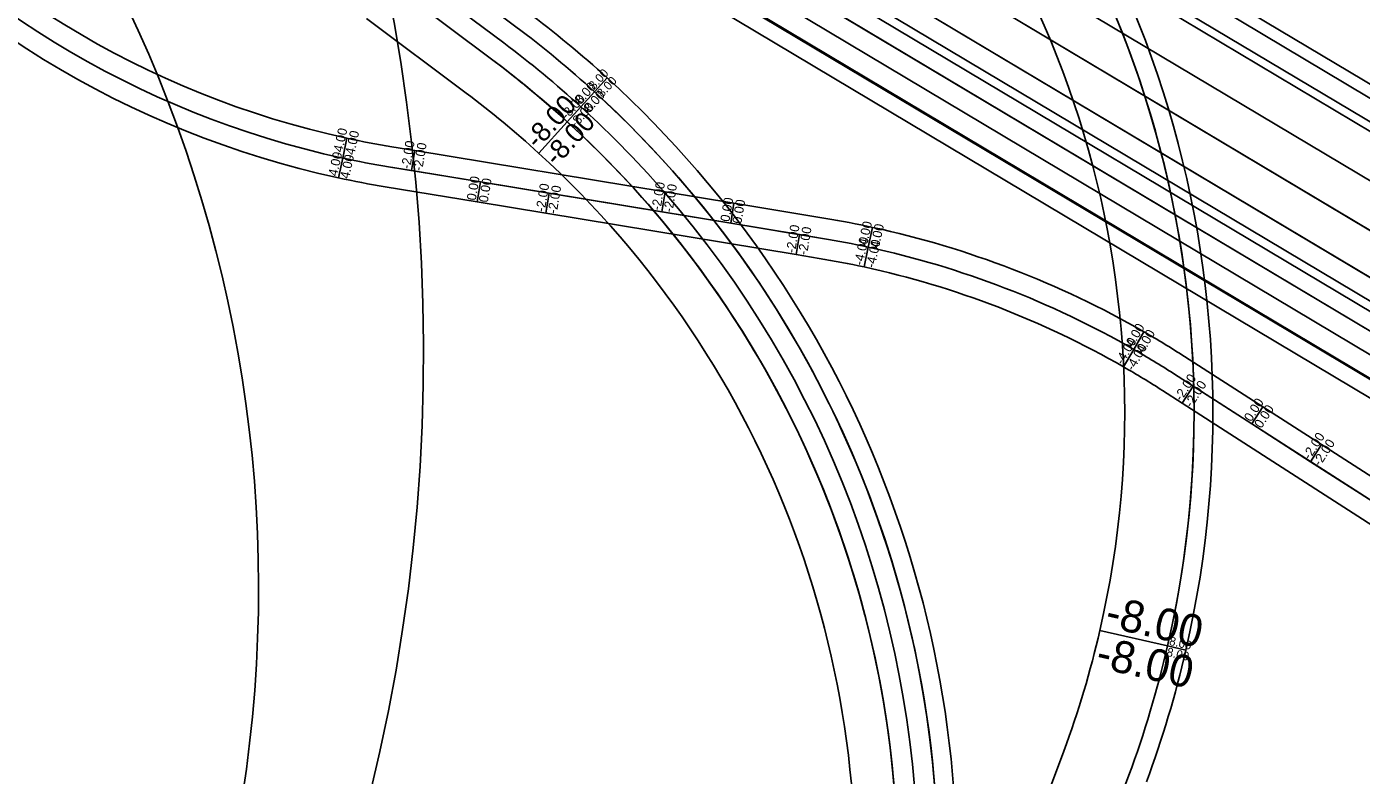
# Model space of a CAD drawing. Extents: x 2342222 to 2351711, y 366548 to 372860.
# Drawn here: x 2346266 to 2347057, y 369068 to 369511 of the extents above; entities that cross this region are included whole.
import ezdxf

# ---------------------------------------------------------------- set-up
doc = ezdxf.new("R2010")
doc.units = 0
for name, color, linetype in [('RD_HC_Cl', 7, 'Continuous'), ('RD_PD_Final_LnLine', 7, 'Continuous'), ('RD_PD_SuperShp_BL_EB_526', 7, 'Continuous'), ('RD_PD_SuperShp_BL_WB_526', 7, 'Continuous'), ('RD_PD_SuperShp_EB_526', 7, 'Continuous'), ('RD_PD_SuperShp_LINE-A', 7, 'Continuous'), ('RD_PD_SuperShp_Line-B', 7, 'Continuous'), ('RD_PD_SuperShp_REL_L-2118', 7, 'Continuous'), ('RD_PD_SuperShp_REL_LINE-3', 7, 'Continuous'), ('RD_PD_SuperShp_WB_526', 7, 'Continuous')]:
    doc.layers.add(name, color=color, linetype=linetype)

msp = doc.modelspace()

# ---------------------------------------------------------------- linework, layer by layer
at = {"layer": 'RD_HC_Cl'}
for centre, radius, start, end in [((2345401.07, 369318.89), 1100, 337.175, 58.13524), ((2345401.07, 369318.89), 1100, 337.175, 58.13524), ((2345603.44, 369178.93), 800, 339.77456, 51.32478), ((2345603.44, 369178.93), 800, 339.77456, 51.32478)]:
    msp.add_arc(centre, radius, start, end, dxfattribs=at)
at = {"layer": 'RD_PD_Final_LnLine'}
msp.add_line((2346236.75, 369794.56), (2347945.19, 368775.26), dxfattribs=at)
msp.add_line((2346236.75, 369794.56), (2347945.19, 368775.26), dxfattribs=at)
msp.add_arc((2346182.01, 369011.56), 600, 321.09378, 53.19179, dxfattribs=at)
at = {"layer": 'RD_PD_SuperShp_BL_EB_526'}
for p, q in [((2348273.55, 368639.71), (2346276.99, 369830.91)), ((2346270.85, 369820.6), (2348267.44, 368629.38)), ((2346351.12, 369814.63), (2348285.99, 368660.23)), ((2348273.55, 368639.71), (2346338.83, 369794.02)), ((2347092.44, 369401.64), (2346692.07, 369640.52)), ((2346679.17, 369618.9), (2347079.55, 369380.03))]:
    msp.add_line(p, q, dxfattribs=at)
at = {"layer": 'RD_PD_SuperShp_BL_WB_526'}
for p, q in [((2348323.93, 368724.15), (2346306.76, 369927.65)), ((2346294.47, 369907.04), (2348311.78, 368703.46)), ((2347105.34, 369423.25), (2346704.96, 369662.13)), ((2346692.07, 369640.52), (2347092.44, 369401.64))]:
    msp.add_line(p, q, dxfattribs=at)
at = {"layer": 'RD_PD_SuperShp_EB_526'}
for p, q in [((2348285.94, 368660.26), (2346335.92, 369823.7)), ((2346323.32, 369803.27), (2348273.49, 368639.75)), ((2346323.62, 369803.09), (2348273.49, 368639.75))]:
    msp.add_line(p, q, dxfattribs=at)
at = {"layer": 'RD_PD_SuperShp_LINE-A'}
for p, q in [((2346901.84, 369153.72), (2346941.92, 369144.5)), ((2346941.92, 369144.5), (2346901.84, 369153.72)), ((2346941.92, 369144.5), (2346952.76, 369142)), ((2346952.76, 369142), (2346941.92, 369144.5)), ((2346880.42, 369082.26), (2346846.34, 368990.65)), ((2346884.88, 368976.31), (2346918.97, 369067.92))]:
    msp.add_line(p, q, dxfattribs=at)
for radius, start, end in [(627.13, 347.0341, 50.18223), (616, 347.0341, 50.18223), (574.88, 347.0341, 50.18223), (616, 347.0341, 25.02373), (574.88, 339.59346, 347.0341), (616, 339.59346, 347.0341), (616, 339.59346, 347.0341), (627.13, 339.59346, 347.0341)]:
    msp.add_arc((2346341.62, 369282.71), radius, start, end, dxfattribs=at)
at = {"layer": 'RD_PD_SuperShp_Line-B'}
for p, q in [((2346496.91, 369555.28), (2346555.87, 369511.16)), ((2346548.69, 369501.55), (2346489.72, 369545.67)), ((2346489.72, 369545.67), (2346548.69, 369501.55)), ((2346541.5, 369491.94), (2346482.53, 369536.06)), ((2346541.5, 369491.94), (2346482.53, 369536.06)), ((2346467.48, 369515.95), (2346526.44, 369471.83)), ((2346602.5, 369472.61), (2346610, 369480.83)), ((2346610, 369480.83), (2346602.5, 369472.61)), ((2346602.5, 369472.61), (2346594.41, 369463.74)), ((2346594.41, 369463.74), (2346602.5, 369472.61)), ((2346594.41, 369463.74), (2346586.33, 369454.87)), ((2346586.33, 369454.87), (2346594.41, 369463.74)), ((2346569.4, 369436.31), (2346586.33, 369454.87)), ((2346586.33, 369454.87), (2346569.4, 369436.31))]:
    msp.add_line(p, q, dxfattribs=at)
for radius, start, end in [(635.13, 47.63463, 53.19179), (624, 47.63463, 53.19179), (624, 47.63463, 53.19179), (612, 47.63463, 53.19179), (612, 47.63463, 53.19179), (600, 47.63463, 53.19179), (600, 47.63463, 53.19179), (635.13, 353.08954, 47.63463), (574.88, 47.63463, 53.19179), (624, 326.65285, 47.63463), (624, 353.08954, 47.63463), (612, 326.65285, 47.63463), (612, 326.65285, 47.63463), (600, 326.65285, 47.63463), (600, 353.08954, 47.63463), (574.88, 353.08954, 47.63463)]:
    msp.add_arc((2346182.01, 369011.56), radius, start, end, dxfattribs=at)
at = {"layer": 'RD_PD_SuperShp_REL_L-2118'}
for p, q in [((2346455.86, 369445.11), (2346453.32, 369433.38)), ((2346455.86, 369445.11), (2346453.32, 369433.38)), ((2346495.98, 369437.81), (2346482.37, 369440.05)), ((2346450.78, 369421.65), (2346453.32, 369433.38)), ((2346450.78, 369421.65), (2346453.32, 369433.38)), ((2346494.02, 369425.97), (2346495.98, 369437.81)), ((2346494.02, 369425.97), (2346495.98, 369437.81)), ((2346495.98, 369437.81), (2346644.26, 369413.35)), ((2346480.41, 369428.21), (2346494.02, 369425.97)), ((2346480.41, 369428.21), (2346534.85, 369419.23)), ((2346642.31, 369401.51), (2346494.02, 369425.97)), ((2346532.9, 369407.39), (2346478.46, 369416.37)), ((2346534.85, 369419.23), (2346532.9, 369407.39)), ((2346532.9, 369407.39), (2346534.85, 369419.23)), ((2346534.85, 369419.23), (2346575.67, 369412.5)), ((2346575.67, 369412.5), (2346573.72, 369400.66)), ((2346573.72, 369400.66), (2346575.67, 369412.5)), ((2346575.67, 369412.5), (2346723.96, 369388.04)), ((2346644.26, 369413.35), (2346642.31, 369401.51)), ((2346642.31, 369401.51), (2346644.26, 369413.35)), ((2346644.26, 369413.35), (2346685.08, 369406.62)), ((2346573.72, 369400.66), (2346532.9, 369407.39)), ((2346722, 369376.2), (2346573.72, 369400.66)), ((2346683.13, 369394.78), (2346642.31, 369401.51)), ((2346685.08, 369406.62), (2346683.13, 369394.78)), ((2346683.13, 369394.78), (2346685.08, 369406.62)), ((2346685.08, 369406.62), (2346739.54, 369397.63)), ((2346737.58, 369385.79), (2346683.13, 369394.78)), ((2346767.21, 369392.36), (2346764.66, 369380.63)), ((2346764.66, 369380.63), (2346767.21, 369392.36)), ((2346723.96, 369388.04), (2346722, 369376.2)), ((2346722, 369376.2), (2346723.96, 369388.04)), ((2346723.96, 369388.04), (2346737.58, 369385.79)), ((2346735.63, 369373.95), (2346722, 369376.2)), ((2346764.66, 369380.63), (2346762.12, 369368.9)), ((2346762.12, 369368.9), (2346764.66, 369380.63)), ((2346927.86, 369330.53), (2346921.89, 369320.13)), ((2346921.89, 369320.13), (2346927.86, 369330.53)), ((2346921.89, 369320.13), (2346915.91, 369309.72)), ((2346921.89, 369320.13), (2346915.91, 369309.72)), ((2346951.94, 369315.89), (2346998.36, 369286.06)), ((2346991.87, 369275.97), (2346945.46, 369305.8)), ((2346957.06, 369298.34), (2346945.46, 369305.8)), ((2346950.57, 369288.24), (2346957.06, 369298.34)), ((2346950.57, 369288.24), (2346957.06, 369298.34)), ((2346957.06, 369298.34), (2347131.86, 369185.99)), ((2346938.97, 369295.7), (2346950.57, 369288.24)), ((2347125.37, 369175.89), (2346950.57, 369288.24)), ((2346998.36, 369286.06), (2346991.87, 369275.97)), ((2346991.87, 369275.97), (2346998.36, 369286.06)), ((2346998.36, 369286.06), (2347033.16, 369263.69)), ((2347026.67, 369253.6), (2346991.87, 369275.97)), ((2347033.16, 369263.69), (2347026.67, 369253.6)), ((2347026.67, 369253.6), (2347033.16, 369263.69)), ((2347033.16, 369263.69), (2347138.35, 369196.08)), ((2347131.86, 369185.99), (2347026.67, 369253.6))]:
    msp.add_line(p, q, dxfattribs=at)
for centre, radius, start, end in [((2346569.92, 369970.88), 538, 219.20131, 257.76033), ((2346569.92, 369970.88), 550, 219.20131, 257.76033), ((2346569.92, 369970.88), 550, 219.20131, 257.76033), ((2346569.92, 369970.88), 562, 219.20131, 257.76033), ((2346569.92, 369970.88), 538, 257.76033, 260.63391), ((2346569.92, 369970.88), 550, 257.76033, 260.63391), ((2346569.92, 369970.88), 550, 257.76033, 260.63391), ((2346569.92, 369970.88), 562, 257.76033, 260.63391), ((2346648.08, 368843.13), 562, 77.76188, 80.63391), ((2346648.08, 368843.13), 562, 60.14291, 77.76188), ((2346648.08, 368843.13), 550, 77.76188, 80.63391), ((2346648.08, 368843.13), 550, 77.76188, 80.63391), ((2346648.08, 368843.13), 550, 60.14291, 77.76188), ((2346648.08, 368843.13), 550, 60.14291, 77.76188), ((2346648.08, 368843.13), 538, 77.76188, 80.63391), ((2346648.08, 368843.13), 538, 60.14291, 77.76188), ((2346648.08, 368843.13), 562, 57.26935, 60.14291), ((2346648.08, 368843.13), 550, 57.26935, 60.14291), ((2346648.08, 368843.13), 550, 57.26935, 60.14291), ((2346648.08, 368843.13), 538, 57.26935, 60.14291)]:
    msp.add_arc(centre, radius, start, end, dxfattribs=at)
at = {"layer": 'RD_PD_SuperShp_REL_LINE-3'}
for p, q in [((2347921.67, 368829.56), (2346247.54, 369828.39)), ((2346242.42, 369819.8), (2347800.61, 368890.14)), ((2346242.42, 369819.8), (2347916.54, 368820.98)), ((2347794.46, 368879.84), (2346236.27, 369809.5)), ((2346236.27, 369809.5), (2347871.75, 368833.73)), ((2347865.6, 368823.42), (2346230.12, 369799.19)), ((2346323.68, 369743.38), (2347904.25, 368800.37)), ((2347899.12, 368791.78), (2346318.55, 369734.79))]:
    msp.add_line(p, q, dxfattribs=at)
at = {"layer": 'RD_PD_SuperShp_WB_526'}
msp.add_line((2346189.94, 369975.03), (2349293.25, 368123.51), dxfattribs=at)
msp.add_lwpolyline([(2349305.54, 368144.11), (2347116.84, 369449.97), (2347110.69, 369439.66), (2346196.09, 369985.34)], dxfattribs=at)

# ---------------------------------------------------------------- texts
at = {"layer": 'RD_PD_SuperShp_LINE-A'}
for s, height, p in [('-8.00', 18.917, (2346904.09, 369156.16)), ('-8.00', 18.917, (2346898.55, 369132.11)), ('8.00', 5.118, (2346942.53, 369145.16)), ('8.00', 5.118, (2346941.03, 369138.65))]:
    msp.add_text(s, height=height, rotation=347.0341, dxfattribs=at).set_placement(p)
at = {"layer": 'RD_PD_SuperShp_Line-B'}
for s, height, p in [('8.00', 5.117, (2346602.22, 369473.46)), ('8.00', 5.117, (2346607.15, 369468.96)), ('-8.00', 5.52, (2346586.03, 369455.79)), ('8.00', 5.52, (2346594.11, 369464.66)), ('8.00', 5.52, (2346599.43, 369459.81)), ('-8.00', 11.558, (2346568.77, 369438.23)), ('-8.00', 5.52, (2346591.35, 369450.94)), ('-8.00', 11.558, (2346579.91, 369428.08))]:
    msp.add_text(s, height=height, rotation=47.63463, dxfattribs=at).set_placement(p)
at = {"layer": 'RD_PD_SuperShp_REL_L-2118'}
for s, rotation, p in [('-4.00', 77.76033, (2346452.6, 369434.03)), ('-4.00', 77.76033, (2346459.64, 369432.5)), ('-2.00', 80.63391, (2346493.27, 369426.58)), ('-2.00', 80.63391, (2346500.38, 369425.41)), ('4.00', 77.76033, (2346450.06, 369422.3)), ('4.00', 77.76033, (2346457.09, 369420.78)), ('0.00', 80.63391, (2346532.15, 369408)), ('0.00', 80.63391, (2346539.25, 369406.83)), ('-2.00', 80.63391, (2346572.97, 369401.27)), ('-2.00', 80.63391, (2346580.07, 369400.1)), ('-2.00', 80.63391, (2346641.56, 369402.12)), ('-2.00', 80.63391, (2346648.66, 369400.95)), ('0.00', 80.63391, (2346682.38, 369395.39)), ('0.00', 80.63391, (2346689.48, 369394.21)), ('-2.00', 80.63391, (2346721.25, 369376.81)), ('-2.00', 80.63391, (2346728.36, 369375.64)), ('4.00', 77.76188, (2346763.94, 369381.27)), ('4.00', 77.76188, (2346770.98, 369379.75)), ('-4.00', 77.76188, (2346761.4, 369369.55)), ('-4.00', 77.76188, (2346768.44, 369368.02)), ('4.00', 60.14291, (2346921.4, 369320.96)), ('4.00', 60.14291, (2346927.64, 369317.37)), ('-4.00', 60.14291, (2346915.42, 369310.55)), ('-4.00', 60.14291, (2346921.67, 369306.97)), ('-2.00', 57.26935, (2346950.13, 369289.1)), ('-2.00', 57.26935, (2346956.18, 369285.21)), ('0.00', 57.26935, (2346991.42, 369276.82)), ('0.00', 57.26935, (2346997.48, 369272.93)), ('-2.00', 57.26935, (2347026.23, 369254.46)), ('-2.00', 57.26935, (2347032.28, 369250.56))]:
    msp.add_text(s, height=5.52, rotation=rotation, dxfattribs=at).set_placement(p)

doc.saveas('drawing.dxf')
